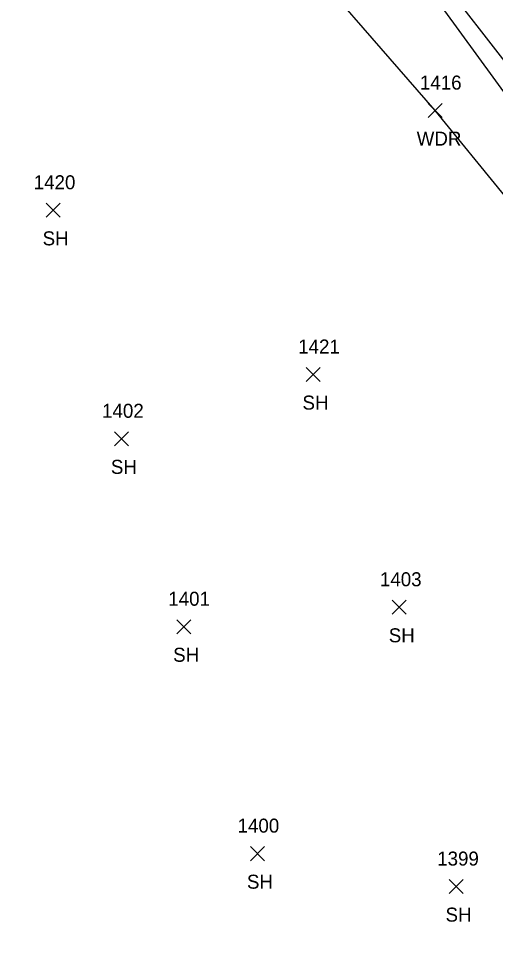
# Model space of a CAD drawing. Extents: x 1653908 to 1654393, y 539913 to 544256.
# Drawn here: x 1653928.6 to 1653996.7, y 541556.9 to 541690.6 of the extents above; entities that cross this region are included whole.
import ezdxf

# ---------------------------------------------------------------- set-up
doc = ezdxf.new("R2010")
doc.units = 0
for name, color, linetype in [('L_A', 7, 'Continuous'), ('L_I', 7, 'Continuous'), ('L_TIC', 7, 'Continuous'), ('LAWA', 7, 'Continuous'), ('LAWE', 7, 'Continuous'), ('LELB', 7, 'Continuous')]:
    doc.layers.add(name, color=color, linetype=linetype)

msp = doc.modelspace()

# ---------------------------------------------------------------- linework, layer by layer
at = {"layer": 'L_TIC'}
for points in [[(1653987.11, 541676.48), (1653989.11, 541678.48)], [(1653989.11, 541676.48), (1653987.11, 541678.48)], [(1653932.56, 541662.25), (1653934.56, 541664.25)], [(1653934.56, 541662.25), (1653932.56, 541664.25)], [(1653969.67, 541638.81), (1653971.67, 541640.81)], [(1653971.67, 541638.81), (1653969.67, 541640.81)], [(1653942.32, 541629.64), (1653944.32, 541631.64)], [(1653944.32, 541629.64), (1653942.32, 541631.64)], [(1653981.99, 541605.6), (1653983.99, 541607.6)], [(1653983.99, 541605.6), (1653981.99, 541607.6)], [(1653951.2, 541602.82), (1653953.2, 541604.82)], [(1653953.2, 541602.82), (1653951.2, 541604.82)], [(1653961.74, 541570.44), (1653963.74, 541572.44)], [(1653963.74, 541570.44), (1653961.74, 541572.44)], [(1653990.1, 541565.74), (1653992.1, 541567.74)], [(1653992.1, 541565.74), (1653990.1, 541567.74)]]:
    msp.add_lwpolyline(points, dxfattribs=at)
at = {"layer": 'LAWA'}
msp.add_lwpolyline([(1654038.91, 541618.25), (1654026.28, 541639.03), (1654008.01, 541653.16), (1653988.11, 541677.48), (1653964.64, 541704.45), (1653928.64, 541724.56)], dxfattribs=at)
at = {"layer": 'LAWE'}
msp.add_lwpolyline([(1654165.75, 541453.3), (1654145.37, 541485.64), (1654128.33, 541517.88), (1654118.98, 541538.06), (1654102.88, 541558.43), (1654087.64, 541571.29), (1654080.69, 541574.23), (1654068.7, 541590.65), (1654047.98, 541616.51), (1654043.58, 541623.07), (1654031.27, 541642.94), (1654001.65, 541675.05), (1653981.82, 541702.27), (1653972.91, 541712.11), (1653946.21, 541722.65), (1653929.33, 541730.47)], dxfattribs=at)
at = {"layer": 'LELB'}
msp.add_lwpolyline([(1654046.04, 541625.31), (1654032.71, 541643.47), (1654003.97, 541676.92), (1653983.75, 541702.94), (1653973.71, 541712.94), (1653947.9, 541724.24), (1653930.46, 541733.9)], dxfattribs=at)

# ---------------------------------------------------------------- texts
at = {"layer": 'L_A'}
for s, p in [('WDR', (1653985.47, 541672.48)), ('SH', (1653932.05, 541658.25)), ('SH', (1653969.16, 541634.81)), ('SH', (1653941.8, 541625.64)), ('SH', (1653981.48, 541601.6)), ('SH', (1653950.69, 541598.82)), ('SH', (1653961.23, 541566.44)), ('SH', (1653989.59, 541561.74))]:
    msp.add_text(s, height=2, dxfattribs=at).set_placement(p)
at = {"layer": 'L_I'}
for s, p in [('1416', (1653985.93, 541680.48)), ('1420', (1653930.78, 541666.25)), ('1421', (1653968.55, 541642.81)), ('1402', (1653940.54, 541633.64)), ('1403', (1653980.22, 541609.6)), ('1401', (1653950, 541606.82)), ('1400', (1653959.89, 541574.44)), ('1399', (1653988.4, 541569.74))]:
    msp.add_text(s, height=2, dxfattribs=at).set_placement(p)

doc.saveas('drawing.dxf')
